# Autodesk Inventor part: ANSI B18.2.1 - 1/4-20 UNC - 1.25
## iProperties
Comments: To add or edit properties for Autodesk Inventor files, use iProperties.
Created: 2005-06
Part Number: ANSI B18.2.1 - 1/4-20 UNC - 1.25
Vendor: Autodesk Inc.
Document SubType Name: Modeling
Designer: John Blackburn
Material: Default
Description: Hex Cap Screw
Standard: ANSI B18.2.1
Alert: To add or edit properties for Autodesk Inventor files, use iProperties.
Control State: 0
Master: False
Checked Out: False
Shininess: 64.0
Length Units: 11272
Angle Units: 11279
Time Units: 11290
Mass Units: 11286
Length Display Precision: 3
Angle Display Precision: 2
Compacted: True
EGR: 3
Classification: un/spsc 31161513
Density: 0.0
Volumn: 0.0
Area: 0.0
PropertySet Name: Model Information
Author: John Blackburn
Revision Number: 8
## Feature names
1. Body [Revolution]
2. Head [Extrusion]
3. Chamfer1 [Revolution]
4. Chamfer2
